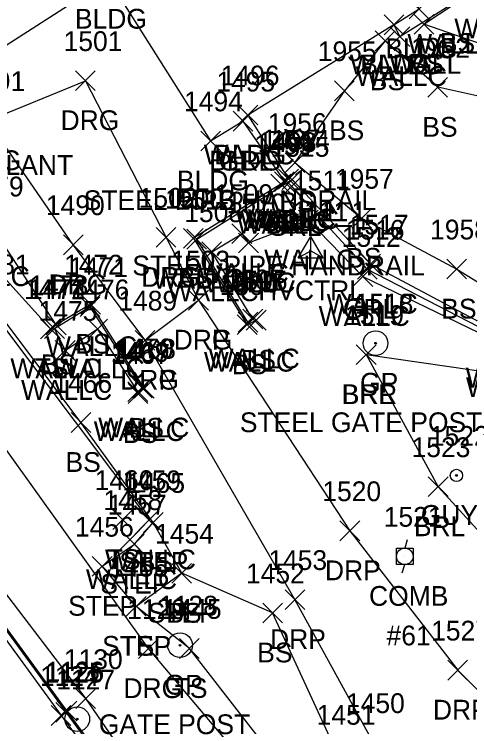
# Model space of a CAD drawing. Extents: x 1647133 to 1649138, y 411736 to 414924.
# Drawn here: x 1648764.3 to 1648810.3, y 412103.5 to 412175.6 of the extents above; entities that cross this region are included whole.
import ezdxf

# ---------------------------------------------------------------- set-up
doc = ezdxf.new("R2010")
doc.units = 0
for name, color, linetype in [('C_A', 7, 'Continuous'), ('C_I', 7, 'Continuous'), ('CPSM', 7, 'Continuous'), ('L_A', 7, 'Continuous'), ('L_C', 7, 'Continuous'), ('L_I', 7, 'Continuous'), ('L_TIC', 7, 'Continuous'), ('LABL', 7, 'Continuous'), ('LBC', 7, 'Continuous'), ('LBF', 7, 'Continuous'), ('LELB', 7, 'Continuous'), ('LW', 7, 'Continuous'), ('R_A', 7, 'Continuous'), ('R_C', 7, 'Continuous'), ('R_I', 7, 'Continuous'), ('R_TIC', 7, 'Continuous'), ('RDG', 7, 'Continuous'), ('RDP', 7, 'Continuous'), ('RGP', 7, 'Continuous'), ('RGR', 7, 'Continuous'), ('U_A', 7, 'Continuous'), ('U_C', 7, 'Continuous'), ('U_I', 7, 'Continuous'), ('UP', 7, 'Continuous'), ('UPGW', 7, 'Continuous')]:
    doc.layers.add(name, color=color, linetype=linetype)

msp = doc.modelspace()

# ---------------------------------------------------------------- linework, layer by layer
at = {"layer": 'CPSM'}
for p, q in [((1648792.981, 412150.926), (1648794.231, 412153.091)), ((1648792.982, 412150.926), (1648794.232, 412153.091)), ((1648792.982, 412150.926), (1648794.232, 412153.091)), ((1648792.982, 412150.926), (1648794.232, 412153.091)), ((1648795.481, 412150.926), (1648794.231, 412153.091)), ((1648794.232, 412151.647), (1648794.231, 412153.091)), ((1648795.482, 412150.926), (1648794.232, 412153.091)), ((1648794.232, 412151.647), (1648794.232, 412153.091)), ((1648795.482, 412150.926), (1648794.232, 412153.091)), ((1648794.232, 412151.647), (1648794.232, 412153.091)), ((1648795.482, 412150.926), (1648794.232, 412153.091)), ((1648794.232, 412151.647), (1648794.232, 412153.091)), ((1648792.981, 412150.926), (1648794.232, 412151.647)), ((1648792.982, 412150.926), (1648794.232, 412151.647)), ((1648792.982, 412150.926), (1648794.232, 412151.647)), ((1648792.982, 412150.926), (1648794.232, 412151.647)), ((1648794.232, 412151.647), (1648794.232, 412151.647)), ((1648794.232, 412151.647), (1648795.482, 412150.926)), ((1648794.232, 412151.647), (1648794.232, 412151.647)), ((1648794.232, 412151.647), (1648795.482, 412150.926)), ((1648794.232, 412151.647), (1648794.232, 412151.647)), ((1648794.232, 412151.647), (1648795.482, 412150.926)), ((1648794.232, 412151.647), (1648794.232, 412151.647)), ((1648794.232, 412151.647), (1648795.481, 412150.926)), ((1648792.981, 412150.926), (1648795.481, 412150.926)), ((1648792.982, 412150.926), (1648795.482, 412150.926)), ((1648792.982, 412150.926), (1648795.482, 412150.926)), ((1648792.982, 412150.926), (1648795.482, 412150.926))]:
    msp.add_line(p, q, dxfattribs=at)
at = {"layer": 'L_TIC'}
for points in [[(1648804.191, 412175.13), (1648806.191, 412177.13)], [(1648806.191, 412175.13), (1648804.191, 412177.13)], [(1648801.657, 412173.507), (1648803.657, 412175.507)], [(1648803.657, 412173.507), (1648801.657, 412175.507)], [(1648801.657, 412173.507), (1648803.657, 412175.507)], [(1648803.657, 412173.507), (1648801.657, 412175.507)], [(1648804.688, 412173.564), (1648806.688, 412175.564)], [(1648806.688, 412173.564), (1648804.688, 412175.564)], [(1648804.688, 412173.564), (1648806.688, 412175.564)], [(1648806.688, 412173.564), (1648804.688, 412175.564)], [(1648802.245, 412172.325), (1648804.245, 412174.325)], [(1648804.245, 412172.325), (1648802.245, 412174.325)], [(1648800.769, 412171.895), (1648802.769, 412173.895)], [(1648802.769, 412171.895), (1648800.769, 412173.895)], [(1648806.082, 412167.189), (1648808.082, 412169.189)], [(1648808.082, 412167.189), (1648806.082, 412169.189)], [(1648796.645, 412166.837), (1648798.645, 412168.837)], [(1648798.645, 412166.837), (1648796.645, 412168.837)], [(1648786.878, 412164.384), (1648788.878, 412166.384)], [(1648788.878, 412164.384), (1648786.878, 412166.384)], [(1648786.878, 412164.384), (1648788.878, 412166.384)], [(1648788.878, 412164.384), (1648786.878, 412166.384)], [(1648786.386, 412163.765), (1648788.386, 412165.765)], [(1648788.386, 412163.765), (1648786.386, 412165.765)], [(1648783.115, 412161.764), (1648785.115, 412163.764)], [(1648785.115, 412161.764), (1648783.115, 412163.764)], [(1648791.644, 412159.569), (1648793.644, 412161.569)], [(1648793.644, 412159.569), (1648791.644, 412161.569)], [(1648790.993, 412157.91), (1648792.993, 412159.91)], [(1648792.993, 412157.91), (1648790.993, 412159.91)], [(1648791.342, 412157.855), (1648793.342, 412159.855)], [(1648793.342, 412157.855), (1648791.342, 412159.855)], [(1648790.209, 412157.398), (1648792.209, 412159.398)], [(1648792.209, 412157.398), (1648790.209, 412159.398)], [(1648790.209, 412157.398), (1648792.209, 412159.398)], [(1648792.209, 412157.398), (1648790.209, 412159.398)], [(1648790.575, 412157.646), (1648792.575, 412159.646)], [(1648792.575, 412157.646), (1648790.575, 412159.646)], [(1648792.992, 412153.764), (1648794.992, 412155.764)], [(1648794.992, 412153.764), (1648792.992, 412155.764)], [(1648798.379, 412153.937), (1648800.379, 412155.937)], [(1648800.379, 412153.937), (1648798.379, 412155.937)], [(1648786.27, 412152.379), (1648788.27, 412154.379)], [(1648788.27, 412152.379), (1648786.27, 412154.379)], [(1648781.368, 412151.917), (1648783.368, 412153.917)], [(1648783.368, 412151.917), (1648781.368, 412153.917)], [(1648781.709, 412151.826), (1648783.709, 412153.826)], [(1648783.709, 412151.826), (1648781.709, 412153.826)], [(1648786.94, 412151.444), (1648788.94, 412153.444)], [(1648788.94, 412151.444), (1648786.94, 412153.444)], [(1648783.217, 412150.553), (1648785.217, 412152.553)], [(1648785.217, 412150.553), (1648783.217, 412152.553)], [(1648799.309, 412149.294), (1648801.309, 412151.294)], [(1648801.309, 412149.294), (1648799.309, 412151.294)], [(1648808.001, 412148.8), (1648810.001, 412150.8)], [(1648810.001, 412148.8), (1648808.001, 412150.8)], [(1648798.503, 412148.051), (1648800.503, 412150.051)], [(1648800.503, 412148.051), (1648798.503, 412150.051)], [(1648770.92, 412144.992), (1648772.92, 412146.992)], [(1648772.92, 412144.992), (1648770.92, 412146.992)], [(1648770.979, 412145.245), (1648772.979, 412147.245)], [(1648772.979, 412145.245), (1648770.979, 412147.245)], [(1648786.891, 412143.427), (1648788.891, 412145.427)], [(1648788.891, 412143.427), (1648786.891, 412145.427)], [(1648786.891, 412143.427), (1648788.891, 412145.427)], [(1648788.891, 412143.427), (1648786.891, 412145.427)], [(1648787.377, 412143.745), (1648789.377, 412145.745)], [(1648789.377, 412143.745), (1648787.377, 412145.745)], [(1648787.715, 412143.628), (1648789.715, 412145.628)], [(1648789.715, 412143.628), (1648787.715, 412145.628)], [(1648766.918, 412142.759), (1648768.918, 412144.759)], [(1648768.918, 412142.759), (1648766.918, 412144.759)], [(1648767.322, 412142.763), (1648769.322, 412144.763)], [(1648769.322, 412142.763), (1648767.322, 412144.763)], [(1648767.484, 412143.159), (1648769.484, 412145.159)], [(1648769.484, 412143.159), (1648767.484, 412145.159)], [(1648771.685, 412142.743), (1648773.685, 412144.743)], [(1648773.685, 412142.743), (1648771.685, 412144.743)], [(1648771.685, 412142.743), (1648773.685, 412144.743)], [(1648773.685, 412142.743), (1648771.685, 412144.743)], [(1648786.809, 412143.168), (1648788.809, 412145.168)], [(1648788.809, 412143.168), (1648786.809, 412145.168)], [(1648768.399, 412140.568), (1648770.399, 412142.568)], [(1648770.399, 412140.568), (1648768.399, 412142.568)], [(1648798.847, 412140.142), (1648800.847, 412142.142)], [(1648800.847, 412140.142), (1648798.847, 412142.142)], [(1648798.847, 412140.142), (1648800.847, 412142.142)], [(1648800.847, 412140.142), (1648798.847, 412142.142)], [(1648775.748, 412136.407), (1648777.748, 412138.407)], [(1648777.748, 412136.407), (1648775.748, 412138.407)], [(1648775.748, 412136.407), (1648777.748, 412138.407)], [(1648777.748, 412136.407), (1648775.748, 412138.407)], [(1648775.777, 412136.209), (1648777.777, 412138.209)], [(1648777.777, 412136.209), (1648775.777, 412138.209)], [(1648776.204, 412136.77), (1648778.204, 412138.77)], [(1648778.204, 412136.77), (1648776.204, 412138.77)], [(1648776.389, 412136.737), (1648778.389, 412138.737)], [(1648778.389, 412136.737), (1648776.389, 412138.737)], [(1648769.991, 412133.28), (1648771.991, 412135.28)], [(1648771.991, 412133.28), (1648769.991, 412135.28)], [(1648806.127, 412126.778), (1648808.127, 412128.778)], [(1648808.127, 412126.778), (1648806.127, 412128.778)], [(1648774.21, 412123.445), (1648776.21, 412125.445)], [(1648776.21, 412123.445), (1648774.21, 412125.445)], [(1648776.88, 412123.426), (1648778.88, 412125.426)], [(1648778.88, 412123.426), (1648776.88, 412125.426)], [(1648777.316, 412123.162), (1648779.316, 412125.162)], [(1648779.316, 412123.162), (1648777.316, 412125.162)], [(1648777.316, 412123.162), (1648779.316, 412125.162)], [(1648779.316, 412123.162), (1648777.316, 412125.162)], [(1648777.316, 412123.162), (1648779.316, 412125.162)], [(1648779.316, 412123.162), (1648777.316, 412125.162)], [(1648774.963, 412121.426), (1648776.963, 412123.426)], [(1648776.963, 412121.426), (1648774.963, 412123.426)], [(1648775.405, 412120.971), (1648777.405, 412122.971)], [(1648777.405, 412120.971), (1648775.405, 412122.971)], [(1648772.137, 412118.731), (1648774.137, 412120.731)], [(1648774.137, 412118.731), (1648772.137, 412120.731)], [(1648780.189, 412118.025), (1648782.189, 412120.025)], [(1648782.189, 412118.025), (1648780.189, 412120.025)], [(1648780.189, 412118.025), (1648782.189, 412120.025)], [(1648782.189, 412118.025), (1648780.189, 412120.025)], [(1648780.189, 412118.025), (1648782.189, 412120.025)], [(1648782.189, 412118.025), (1648780.189, 412120.025)], [(1648775.578, 412114.68), (1648777.578, 412116.68)], [(1648777.578, 412114.68), (1648775.578, 412116.68)], [(1648775.578, 412114.68), (1648777.578, 412116.68)], [(1648777.578, 412114.68), (1648775.578, 412116.68)], [(1648789.38, 412114.008), (1648791.38, 412116.008)], [(1648791.38, 412114.008), (1648789.38, 412116.008)], [(1648780.967, 412110.414), (1648782.967, 412112.414)], [(1648782.967, 412110.414), (1648780.967, 412112.414)], [(1648768.46, 412103.966), (1648770.46, 412105.966)], [(1648770.46, 412103.966), (1648768.46, 412105.966)], [(1648768.584, 412104.08), (1648770.584, 412106.08)], [(1648770.584, 412104.08), (1648768.584, 412106.08)], [(1648767.983, 412103.635), (1648769.983, 412105.635)], [(1648769.983, 412103.635), (1648767.983, 412105.635)]]:
    msp.add_lwpolyline(points, dxfattribs=at)
at = {"layer": 'LABL'}
for points in [[(1648799.847, 412141.142), (1648807.127, 412127.778), (1648818.199, 412115.65), (1648824.968, 412111.366), (1648838.944, 412123.578)], [(1648799.847, 412141.142), (1648813.37, 412139.189), (1648824.717, 412133.505), (1648838.944, 412123.578)]]:
    msp.add_lwpolyline(points, dxfattribs=at)
at = {"layer": 'LBC'}
for points in [[(1648802.657, 412174.507), (1648805.191, 412176.13), (1648795.837, 412191.432)], [(1648756.492, 412168.261), (1648756.978, 412168.328), (1648773.797, 412179.125), (1648784.115, 412162.764), (1648787.386, 412164.765), (1648787.878, 412165.384)]]:
    msp.add_lwpolyline(points, dxfattribs=at)
at = {"layer": 'LBF'}
for points in [[(1648781.189, 412119.025), (1648776.578, 412115.68), (1648773.137, 412119.731), (1648776.405, 412121.971), (1648778.316, 412124.162)], [(1648781.189, 412119.025), (1648778.316, 412124.162)]]:
    msp.add_lwpolyline(points, dxfattribs=at)
at = {"layer": 'LELB'}
for points in [[(1648805.688, 412174.564), (1648808.859, 412176.673), (1648802.832, 412186.514), (1648798.472, 412193.595), (1648799.508, 412194.344)], [(1648885.787, 412152.041), (1648870.49, 412148.148), (1648856.957, 412156.187), (1648842.553, 412158.499), (1648828.356, 412162.203), (1648812.843, 412166.91), (1648807.082, 412168.189), (1648801.769, 412172.895), (1648797.645, 412167.837), (1648792.644, 412160.569), (1648799.379, 412154.937), (1648809.001, 412149.8), (1648818.426, 412144.032), (1648829.711, 412141.28), (1648839.461, 412137.596), (1648848.65, 412137.378), (1648855.669, 412134.7), (1648862.03, 412127.85), (1648868.869, 412121.213), (1648875.311, 412117.612), (1648882.604, 412109.86)], [(1648776.777, 412137.209), (1648777.389, 412137.737), (1648771.979, 412146.245), (1648768.484, 412144.159), (1648761.95, 412154.153), (1648753.705, 412165.912), (1648756.978, 412168.328)], [(1648778.316, 412124.162), (1648770.991, 412134.28), (1648761.983, 412146.261), (1648749.733, 412162.682)], [(1648791.209, 412158.398), (1648782.368, 412152.917), (1648787.809, 412144.168), (1648788.715, 412144.628)], [(1648767.918, 412143.759), (1648760.308, 412152.148)], [(1648745.05, 412138.635), (1648769.584, 412105.08), (1648788.529, 412079.455), (1648789.895, 412077.48), (1648789.743, 412077.373)], [(1648801.085, 412088.497), (1648796.966, 412100.703), (1648790.38, 412115.008), (1648781.189, 412119.025)], [(1648801.085, 412088.497), (1648793.512, 412096.572), (1648781.967, 412111.414), (1648776.578, 412115.68)]]:
    msp.add_lwpolyline(points, dxfattribs=at)
at = {"layer": 'LW'}
for points in [[(1648802.657, 412174.507), (1648803.245, 412173.325), (1648808.466, 412176.6), (1648798.148, 412193.142), (1648795.837, 412191.432)], [(1648802.657, 412174.507), (1648787.878, 412165.384)], [(1648842.521, 412160.657), (1648830.932, 412165.818), (1648805.688, 412174.564)], [(1648787.878, 412165.384), (1648791.993, 412158.91), (1648791.575, 412158.646), (1648791.209, 412158.398)], [(1648775.963, 412122.426), (1648777.88, 412124.426), (1648759.28, 412149.161), (1648748.932, 412162.964)], [(1648787.891, 412144.427), (1648782.709, 412152.826), (1648792.342, 412158.855), (1648800.309, 412150.294), (1648814.37, 412142.815), (1648825.933, 412136.828), (1648844.3, 412127.977), (1648844.864, 412126.782)], [(1648787.891, 412144.427), (1648788.377, 412144.745), (1648784.217, 412151.553), (1648787.27, 412153.379), (1648787.94, 412152.444), (1648793.992, 412154.764), (1648799.503, 412149.051), (1648814.399, 412141.844), (1648825.589, 412136.181), (1648844.864, 412126.782)], [(1648776.748, 412137.407), (1648777.204, 412137.77), (1648771.92, 412145.992), (1648768.322, 412143.763), (1648769.399, 412141.568), (1648772.685, 412143.743)], [(1648776.748, 412137.407), (1648772.685, 412143.743)], [(1648745.173, 412138.304), (1648744.678, 412137.988), (1648768.983, 412104.635), (1648787.771, 412079.188), (1648789.161, 412077.085), (1648789.611, 412077.412)], [(1648745.173, 412138.304), (1648769.46, 412104.966), (1648788.252, 412079.392), (1648789.611, 412077.412)]]:
    msp.add_lwpolyline(points, dxfattribs=at)
at = {"layer": 'R_TIC'}
for points in [[(1648770.447, 412167.861), (1648772.447, 412169.861)], [(1648772.447, 412167.861), (1648770.447, 412169.861)], [(1648786.386, 412163.765), (1648788.386, 412165.765)], [(1648788.386, 412163.765), (1648786.386, 412165.765)], [(1648790.575, 412157.646), (1648792.575, 412159.646)], [(1648792.575, 412157.646), (1648790.575, 412159.646)], [(1648791.303, 412157.164), (1648793.303, 412159.164)], [(1648793.303, 412157.164), (1648791.303, 412159.164)], [(1648778.603, 412152.007), (1648780.603, 412154.007)], [(1648780.603, 412152.007), (1648778.603, 412154.007)], [(1648769.225, 412151.258), (1648771.225, 412153.258)], [(1648771.225, 412151.258), (1648769.225, 412153.258)], [(1648798.95, 412148.784), (1648800.95, 412150.784)], [(1648800.95, 412148.784), (1648798.95, 412150.784)], [(1648781.888, 412145.657), (1648783.888, 412147.657)], [(1648783.888, 412145.657), (1648781.888, 412147.657)], [(1648781.888, 412145.657), (1648783.888, 412147.657)], [(1648783.888, 412145.657), (1648781.888, 412147.657)], [(1648776.478, 412141.603), (1648778.478, 412143.603)], [(1648778.478, 412141.603), (1648776.478, 412143.603)], [(1648776.478, 412141.603), (1648778.478, 412143.603)], [(1648778.478, 412141.603), (1648776.478, 412143.603)], [(1648797.186, 412122.321), (1648799.186, 412124.321)], [(1648799.186, 412122.321), (1648797.186, 412124.321)], [(1648791.637, 412115.358), (1648793.637, 412117.358)], [(1648793.637, 412115.358), (1648791.637, 412117.358)], [(1648776.802, 412110.4), (1648778.802, 412112.4)], [(1648778.802, 412110.4), (1648776.802, 412112.4)], [(1648808.106, 412108.222), (1648810.106, 412110.222)], [(1648810.106, 412108.222), (1648808.106, 412110.222)], [(1648770.48, 412105.331), (1648772.48, 412107.331)], [(1648772.48, 412105.331), (1648770.48, 412107.331)]]:
    msp.add_lwpolyline(points, dxfattribs=at)
at = {"layer": 'RDG'}
for points in [[(1648665.441, 412272.797), (1648687.368, 412235.883), (1648707.36, 412207.822), (1648732.67, 412172.62), (1648752.06, 412147.321), (1648777.802, 412111.4), (1648801.739, 412083.078)], [(1648657.183, 412267.776), (1648679.811, 412230.814), (1648700.282, 412202.253), (1648725.639, 412167.846), (1648744.327, 412141.94), (1648771.48, 412106.331), (1648789.563, 412079.997), (1648790.942, 412077.169)], [(1648777.478, 412142.603), (1648770.225, 412152.258), (1648761.536, 412164.81), (1648771.447, 412168.861), (1648779.603, 412153.007), (1648782.888, 412146.657)]]:
    msp.add_lwpolyline(points, dxfattribs=at)
at = {"layer": 'RDP'}
msp.add_lwpolyline([(1648808.637, 412087.198), (1648800.581, 412101.88), (1648792.637, 412116.358), (1648777.478, 412142.603), (1648782.888, 412146.657), (1648798.186, 412123.321), (1648809.106, 412109.222), (1648819.325, 412099.049), (1648820.622, 412097.822), (1648822.814, 412097.685)], dxfattribs=at)
at = {"layer": 'RGP'}
for p, q in [((1648800.792, 412142.301), (1648800.792, 412142.301)), ((1648781.02, 412111.749), (1648781.02, 412111.749)), ((1648770.622, 412104.27), (1648770.622, 412104.27))]:
    msp.add_line(p, q, dxfattribs=at)
for centre, radius in [((1648800.792, 412142.301), 1.25), ((1648800.792, 412142.301), 0.0833), ((1648781.02, 412111.749), 1.25), ((1648781.02, 412111.749), 0.0833), ((1648770.622, 412104.27), 1.25), ((1648770.622, 412104.27), 0.0833)]:
    msp.add_circle(centre, radius, dxfattribs=at)
at = {"layer": 'RGR'}
for points in [[(1648787.386, 412164.765), (1648791.575, 412158.646)], [(1648792.303, 412158.164), (1648799.95, 412149.784), (1648814.25, 412142.408), (1648825.804, 412136.387), (1648842.827, 412127.982)]]:
    msp.add_lwpolyline(points, dxfattribs=at)
at = {"layer": 'UP'}
for p, q in [((1648803.998, 412122.4), (1648803.748, 412121.566)), ((1648802.914, 412119.9), (1648802.914, 412121.566)), ((1648802.914, 412121.566), (1648804.581, 412121.566)), ((1648804.581, 412121.566), (1648804.581, 412119.9)), ((1648803.748, 412120.733), (1648803.748, 412120.733)), ((1648804.581, 412119.9), (1648802.914, 412119.9)), ((1648803.498, 412119.066), (1648803.748, 412119.9))]:
    msp.add_line(p, q, dxfattribs=at)
msp.add_circle((1648803.748, 412120.733), 0.833, dxfattribs=at)
at = {"layer": 'UPGW'}
for radius in [0.625, 0.0833]:
    msp.add_circle((1648808.975, 412128.925), radius, dxfattribs=at)

# ---------------------------------------------------------------- texts
at = {"layer": 'C_A'}
msp.add_text('HVCTRL', height=2, dxfattribs=at).set_placement((1648788.925, 412146.647))
msp.add_text('HVCTRL', height=2, dxfattribs=at).set_placement((1648788.925, 412146.647))
msp.add_text('HVCTRL', height=2, dxfattribs=at).set_placement((1648788.925, 412146.647))
msp.add_text('HVCTRL', height=2, dxfattribs=at).set_placement((1648788.925, 412146.647))
at = {"layer": 'C_I'}
for s, p in [('111_1', (1648792.421, 412154.647)), ('111', (1648793.571, 412154.647)), ('111', (1648793.571, 412154.647)), ('111', (1648793.571, 412154.647))]:
    msp.add_text(s, height=2, dxfattribs=at).set_placement(p)
at = {"layer": 'L_A'}
for s, p in [('BLDG', (1648770.388, 412174.125)), ('WALL', (1648808.755, 412173.152)), ('WALLC', (1648804.002, 412171.6)), ('BS', (1648807.3, 412171.673)), ('BLDG', (1648801.782, 412171.13)), ('WALLC', (1648798.193, 412169.507)), ('BLDG', (1648799.248, 412169.507)), ('WALL', (1648802.176, 412169.564)), ('BS', (1648804.129, 412169.564)), ('WALLC', (1648798.78, 412168.325)), ('BS', (1648800.21, 412167.895)), ('BS', (1648796.086, 412162.837)), ('BS', (1648805.523, 412163.189)), ('WALLC', (1648783.413, 412160.384)), ('BLDG', (1648784.469, 412160.384)), ('BLDG', (1648783.976, 412159.765)), ('BLDG', (1648780.706, 412157.764)), ('BS', (1648791.085, 412155.569)), ('WALLC', (1648787.111, 412153.646)), ('WALLC', (1648787.528, 412153.91)), ('WALLC', (1648787.878, 412153.855)), ('WALLC', (1648786.744, 412153.398)), ('BS', (1648789.65, 412153.398)), ('BS', (1648797.82, 412149.937)), ('WALLC', (1648789.527, 412149.764)), ('WALLC', (1648782.805, 412148.379)), ('WALLC', (1648756.6, 412148.079)), ('WALLC', (1648778.245, 412147.826)), ('BS', (1648780.808, 412147.917)), ('WALLC', (1648783.475, 412147.444)), ('WALLC', (1648779.752, 412146.553)), ('WALLC', (1648795.845, 412145.294)), ('BS', (1648807.442, 412144.8)), ('WALLC', (1648795.039, 412144.051)), ('BS', (1648770.42, 412141.245)), ('WALLC', (1648767.456, 412140.992)), ('WALLC', (1648783.912, 412139.745)), ('BS', (1648766.925, 412139.159)), ('WALLC', (1648783.426, 412139.427)), ('WALLC', (1648783.426, 412139.427)), ('BS', (1648786.25, 412139.168)), ('BS', (1648787.156, 412139.628)), ('WALLC', (1648763.857, 412138.763)), ('TS', (1648766.327, 412138.759)), ('WALLC', (1648768.22, 412138.743)), ('WALLC', (1648768.22, 412138.743)), ('WALLC', (1648809.905, 412137.815)), ('WALLC', (1648809.934, 412136.844)), ('WALLC', (1648764.935, 412136.568)), ('BRR', (1648797.335, 412136.142)), ('BRL', (1648797.39, 412136.142)), ('WALLC', (1648772.739, 412132.77)), ('BS', (1648775.83, 412132.737)), ('WALLC', (1648772.283, 412132.407)), ('WALLC', (1648772.283, 412132.407)), ('BS', (1648775.218, 412132.209)), ('BS', (1648769.432, 412129.28)), ('BRL', (1648804.671, 412122.778)), ('WALLC', (1648773.415, 412119.426)), ('TS', (1648773.619, 412119.445)), ('STEP', (1648774.875, 412119.162)), ('STEP', (1648774.875, 412119.162)), ('BS', (1648776.757, 412119.162)), ('WALLC', (1648771.499, 412117.426)), ('STEP', (1648772.964, 412116.971)), ('STEP', (1648769.696, 412114.731)), ('STEP', (1648777.748, 412114.025)), ('STEP', (1648777.748, 412114.025)), ('BS', (1648779.63, 412114.025)), ('STEP', (1648773.137, 412110.68)), ('TS', (1648774.987, 412110.68)), ('BS', (1648788.821, 412110.008)), ('TS', (1648780.377, 412106.414))]:
    msp.add_text(s, height=2, dxfattribs=at).set_placement(p)
at = {"layer": 'L_C'}
for s, p in [('BRICK POWER PLANT', (1648741.821, 412159.328)), ('STEEL PIPE HANDRAIL', (1648771.276, 412155.765))]:
    msp.add_text(s, height=2, dxfattribs=at).set_placement(p)
at = {"layer": 'L_I'}
for s, p in [('1955', (1648794.952, 412170.837)), ('1952', (1648804.389, 412171.189)), ('1496', (1648785.13, 412168.384)), ('1496', (1648785.13, 412168.384)), ('1495', (1648784.693, 412167.765)), ('1494', (1648781.422, 412165.764)), ('1956', (1648789.896, 412163.569)), ('1499', (1648788.508, 412161.398)), ('1499', (1648788.508, 412161.398)), ('1498', (1648788.882, 412161.646)), ('1497', (1648789.3, 412161.91)), ('1514', (1648790.216, 412161.855)), ('1511', (1648792.433, 412157.764)), ('1957', (1648796.686, 412157.937)), ('1479', (1648759.249, 412157.153)), ('1509', (1648784.49, 412156.379)), ('1500', (1648779.509, 412155.917)), ('1513', (1648780.583, 412155.826)), ('1510', (1648785.727, 412155.444)), ('1508', (1648781.445, 412154.553)), ('1517', (1648798.183, 412153.294)), ('1958', (1648806.308, 412152.8)), ('1512', (1648797.377, 412152.051)), ('1481', (1648759.857, 412149.261)), ('1472', (1648769.286, 412149.245)), ('1471', (1648769.794, 412148.992)), ('1507', (1648785.605, 412147.745)), ('1473', (1648765.791, 412147.159)), ('1504', (1648785.037, 412147.168)), ('1506', (1648785.064, 412147.427)), ('1506', (1648785.064, 412147.427)), ('1505', (1648785.944, 412147.628)), ('1477', (1648765.225, 412146.759)), ('1474', (1648765.629, 412146.763)), ('1476', (1648769.937, 412146.743)), ('1476', (1648769.937, 412146.743)), ('1475', (1648766.706, 412144.568)), ('1519', (1648797.713, 412144.142)), ('1519', (1648797.713, 412144.142)), ('1470', (1648774.424, 412140.77)), ('1468', (1648774.649, 412140.737)), ('1469', (1648774, 412140.407)), ('1469', (1648774, 412140.407)), ('1467', (1648774.037, 412140.209)), ('1466', (1648768.195, 412137.28)), ('1523', (1648804.435, 412130.778)), ('1460', (1648772.383, 412127.445)), ('1459', (1648775.179, 412127.426)), ('1465', (1648775.576, 412127.162)), ('1465', (1648775.576, 412127.162)), ('1465', (1648775.576, 412127.162)), ('1458', (1648773.271, 412125.426)), ('1457', (1648773.712, 412124.971)), ('1456', (1648770.389, 412122.731)), ('1454', (1648778.496, 412122.025)), ('1454', (1648778.496, 412122.025)), ('1454', (1648778.496, 412122.025)), ('1455', (1648773.885, 412118.68)), ('1455', (1648773.885, 412118.68)), ('1452', (1648787.687, 412118.008)), ('1445', (1648779.274, 412114.414)), ('1126', (1648767.403, 412108.08)), ('1124', (1648766.857, 412107.635)), ('1125', (1648767.334, 412107.966)), ('1451', (1648794.841, 412103.703))]:
    msp.add_text(s, height=2, dxfattribs=at).set_placement(p)
at = {"layer": 'R_A'}
for s, p in [('DRG', (1648768.935, 412163.861)), ('DRG', (1648759.024, 412159.81)), ('GRL', (1648784.929, 412159.765)), ('GRL', (1648789.119, 412153.646)), ('GRL', (1648789.846, 412153.164)), ('DRG', (1648777.091, 412148.007)), ('DRG', (1648767.713, 412147.258)), ('GRL', (1648797.494, 412144.784)), ('DRG', (1648780.376, 412141.657)), ('DRP', (1648780.376, 412141.657)), ('DRG', (1648774.967, 412137.603)), ('DRP', (1648774.967, 412137.603)), ('GP', (1648799.225, 412137.301)), ('DRP', (1648795.675, 412118.321)), ('DRP', (1648790.125, 412111.358)), ('GP', (1648779.453, 412106.749)), ('DRG', (1648775.29, 412106.4)), ('DRP', (1648806.594, 412104.222))]:
    msp.add_text(s, height=2, dxfattribs=at).set_placement(p)
at = {"layer": 'R_C'}
for s, p in [('STEEL PIPE HANDRAIL', (1648776.193, 412149.164)), ('STEEL GATE POST', (1648787.067, 412133.301)), ('GATE POST', (1648772.807, 412102.749))]:
    msp.add_text(s, height=2, dxfattribs=at).set_placement(p)
at = {"layer": 'R_I'}
for s, p in [('1501', (1648769.242, 412171.861)), ('1491', (1648759.41, 412167.81)), ('1495', (1648784.693, 412167.765)), ('1498', (1648788.882, 412161.646)), ('1515', (1648790.177, 412161.164)), ('1502', (1648776.831, 412156.007)), ('1490', (1648767.446, 412155.258)), ('1516', (1648797.769, 412152.784)), ('1503', (1648780.116, 412149.657)), ('1503', (1648780.116, 412149.657)), ('1489', (1648774.778, 412145.603)), ('1489', (1648774.778, 412145.603)), ('1518', (1648798.666, 412145.301)), ('1520', (1648795.407, 412126.321)), ('1453', (1648789.944, 412119.358)), ('1128', (1648778.894, 412114.749)), ('1129', (1648775.668, 412114.4)), ('1527', (1648806.413, 412112.222)), ('1130', (1648769.267, 412109.331)), ('1127', (1648768.496, 412107.27)), ('1450', (1648797.802, 412104.88))]:
    msp.add_text(s, height=2, dxfattribs=at).set_placement(p)
at = {"layer": 'U_A'}
for s, p in [('GUYW', (1648805.369, 412123.925)), ('COMB', (1648800.134, 412115.733))]:
    msp.add_text(s, height=2, dxfattribs=at).set_placement(p)
at = {"layer": 'U_C'}
msp.add_text('#61', height=2, dxfattribs=at).set_placement((1648801.905, 412111.733))
at = {"layer": 'U_I'}
for s, p in [('1522', (1648806.282, 412131.925)), ('1521', (1648801.622, 412123.733))]:
    msp.add_text(s, height=2, dxfattribs=at).set_placement(p)

doc.saveas('drawing.dxf')
